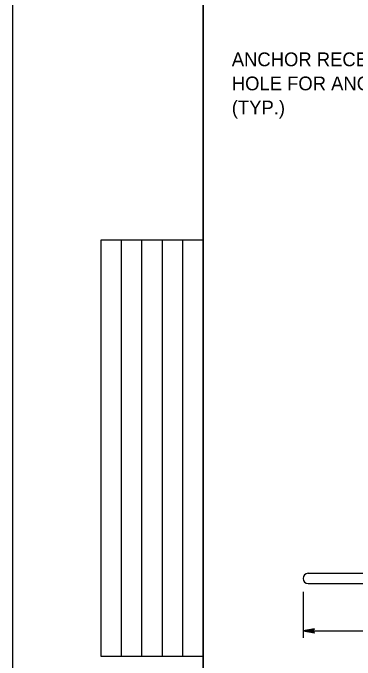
# Model space of a CAD drawing. Extents: x 499883 to 500983, y 499104 to 499764.
# Drawn here: x 499934.8 to 500034.1, y 499383.4 to 499571.4 of the extents above; entities that cross this region are included whole.
import ezdxf

# ---------------------------------------------------------------- set-up
doc = ezdxf.new("R2010")
doc.units = 0
for name, color, linetype in [('1', 7, 'Continuous'), ('24', 7, 'Continuous'), ('41', 7, 'Continuous'), ('5', 7, 'Continuous')]:
    doc.layers.add(name, color=color, linetype=linetype)

msp = doc.modelspace()

# ---------------------------------------------------------------- linework, layer by layer
at = {"layer": '1'}
for p, q in [((499989.94, 499748.64), (499989.94, 499118.64)), ((499989.94, 499748.64), (499989.94, 499118.64)), ((499960.41, 499384.39), (499960.41, 499505.45)), ((499960.41, 499505.45), (499989.94, 499505.45)), ((499966.32, 499384.39), (499966.32, 499505.45)), ((499972.22, 499384.39), (499972.22, 499505.45)), ((499978.13, 499384.39), (499978.13, 499505.45)), ((499984.03, 499384.39), (499984.03, 499505.45)), ((499989.94, 499384.39), (499960.41, 499384.39))]:
    msp.add_line(p, q, dxfattribs=at)
at = {"layer": '24'}
msp.add_lwpolyline([(500018.97, 499391.86), (500022.32, 499391.26), (500021.52, 499391.86), (500022.3, 499392.44), (500018.97, 499391.86), (500019.19, 499391.86), (500022.23, 499391.31), (500021.46, 499391.86), (500022.17, 499392.39), (500019.31, 499391.87), (500019.42, 499391.86), (500022.02, 499391.39), (500021.44, 499391.86), (500022.04, 499392.32), (500019.47, 499391.85), (500019.59, 499391.87), (500021.86, 499391.46), (500021.42, 499391.85), (500021.87, 499392.26), (500019.91, 499391.87), (500020.1, 499391.87), (500021.69, 499391.55), (500021.38, 499391.85), (500021.71, 499392.18), (500020.13, 499391.86), (500020.31, 499391.84), (500021.51, 499391.64), (500021.28, 499391.87), (500021.53, 499392.1), (500020.48, 499391.86), (500020.64, 499391.84), (500021.36, 499391.7), (500021.24, 499391.86), (500021.44, 499392.04), (500020.73, 499391.85), (500021.2, 499391.74), (500021.13, 499391.87), (500021.34, 499392), (500020.85, 499391.87), (500021.16, 499391.8), (500021.03, 499391.9), (500021.18, 499391.96), (500021.03, 499391.86), (500021.11, 499391.85)], dxfattribs=at)
at = {"layer": '41'}
for points in [[(499934.77, 499763.64), (500982.94, 499763.64), (500982.94, 499103.64), (499934.77, 499103.64)], [(499989.94, 499748.64), (500979.94, 499748.64), (500979.94, 499118.64), (499989.94, 499118.64)]]:
    msp.add_lwpolyline(points, close=True, dxfattribs=at)
at = {"layer": '5'}
for p, q in [((500020.47, 499408.59), (500062.68, 499408.59)), ((500020.47, 499405.59), (500062.68, 499405.59)), ((500018.97, 499403.22), (500018.97, 499389.86)), ((500018.97, 499391.86), (500118.39, 499391.86))]:
    msp.add_line(p, q, dxfattribs=at)
msp.add_arc((500020.47, 499407.09), 1.5, 90, 270, dxfattribs=at)

# ---------------------------------------------------------------- texts
for s, p in [('ANCHOR RECESS 1 1/4" DIA.', (499998.29, 499555.93)), ('HOLE FOR ANCHOR PIN', (499998.29, 499548.93)), ('(TYP.) ', (499998.29, 499541.93))]:
    msp.add_text(s, height=4, dxfattribs=at).set_placement(p)

doc.saveas('drawing.dxf')
